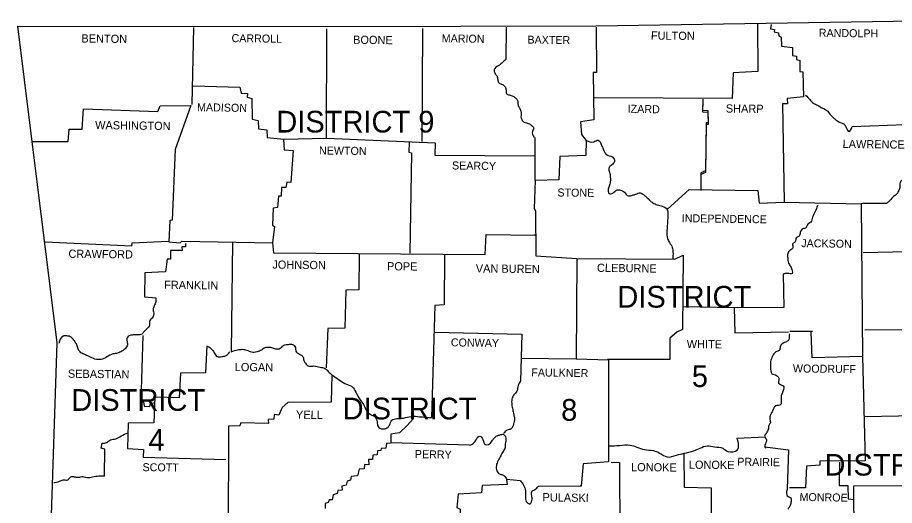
# Model space of a CAD drawing. Extents: x -42408 to 34530, y -43140 to 20491.
# Drawn here: x -17668 to -15135, y 4456 to 5867 of the extents above; entities that cross this region are included whole.
import ezdxf

# ---------------------------------------------------------------- set-up
doc = ezdxf.new("R2010")
doc.units = 0
for name, color, linetype in [('1', 7, 'Continuous'), ('2', 7, 'Continuous'), ('3', 7, 'Continuous')]:
    doc.layers.add(name, color=color, linetype=linetype)

msp = doc.modelspace()

# ---------------------------------------------------------------- linework, layer by layer
at = {"layer": '1'}
msp.add_line((-15436.7, 4960.3), (-15371.2, 4960.3), dxfattribs=at)
for points in [[(-17667.8, 5841.4), (-16777.9, 5840.9), (-15996.9, 5842.5), (-15075.6, 5856.8), (-14648.6, 5866.7)], [(-17667.8, 5841.4), (-17553.9, 4926.7), (-17603.4, 3433.6)], [(-17159.8, 5838.1), (-17164.8, 5615.2)], [(-17160.9, 5669.7), (-17025.5, 5665.3), (-17022.2, 5647.7), (-17003.5, 5647.2), (-17004.1, 5636.1), (-16990.9, 5632.8), (-16989.8, 5572.9), (-16972.7, 5569), (-16971.6, 5545.3), (-16947.4, 5542), (-16946.3, 5520), (-16898.4, 5515.1), (-16775.1, 5517.8), (-16774, 5834.3)], [(-16498.3, 5835.4), (-16500, 5508.5)], [(-16256.1, 5839.2), (-16257.2, 5745.1)], [(-15996.9, 5839.2), (-15995.8, 5708.2), (-16005.2, 5707.7), (-16003.5, 5570.7), (-16042.1, 5565.2), (-16038.8, 5528.3), (-16025.5, 5511.2), (-16026.6, 5467.7), (-16101.5, 5465), (-16104.2, 5397.8), (-16172.5, 5395.6), (-16175.8, 5314.2), (-16171.9, 5307.6), (-16170.3, 5177.7), (-16052.5, 5170), (-16054.2, 4880), (-15960.6, 4877.2), (-15960.6, 4582.2), (-16034.4, 4576.7), (-16039.9, 4511.8), (-16163.7, 4511.2)], [(-15530.8, 5847.5), (-15529.7, 5711), (-15601.2, 5707.1), (-15603.4, 5632.3), (-16001.3, 5634.5)], [(-15491.2, 5846.9), (-15492.8, 5833.7), (-15481.8, 5832.1), (-15482.3, 5825.5), (-15469.7, 5822.7), (-15468.6, 5813.9), (-15462.5, 5810.1), (-15460.9, 5783.6), (-15429.5, 5780.3), (-15429.5, 5756.7), (-15418, 5755), (-15418, 5745.7), (-15408, 5742.9), (-15408.6, 5711), (-15399.8, 5709.3), (-15397.6, 5637.2), (-15444.4, 5632.8), (-15443.8, 5617.4), (-15458.1, 5616.9), (-15453.2, 5332.9), (-15231.4, 5327.9), (-15227.5, 4886.6), (-15372.3, 4882.7), (-15375, 4957)], [(-15688.2, 5630.6), (-15689.3, 5598.7), (-15673.9, 5597.6), (-15673.3, 5562.4), (-15678.8, 5562.4), (-15681, 5423.7), (-15693.7, 5418.2), (-15693.7, 5372)], [(-15688.2, 5625.7), (-15689.3, 5593.8), (-15673.9, 5592.7), (-15673.3, 5557.4), (-15678.8, 5557.4), (-15681, 5418.8), (-15693.7, 5413.3), (-15693.7, 5367)], [(-15619.4, 5629.5), (-15618.8, 5630.1)], [(-17624.3, 5508.5), (-17521.4, 5507.9), (-17518.7, 5544.2), (-17480.7, 5544.2), (-17477.4, 5603.1), (-17262.7, 5595.4), (-17256.1, 5611.9), (-17167.5, 5612.5), (-17212.1, 5484.8), (-17220.9, 5280.6), (-17227.5, 5280.1), (-17230.8, 5218.4), (-17198.4, 5215.7), (-17193.4, 5220.6), (-16930.9, 5215.7), (-16928.1, 5186.5)], [(-15257.3, 5551.9), (-15053.1, 5559.1)], [(-16899.5, 5514), (-16897.3, 5484.3), (-16872, 5482.6), (-16878.6, 5390.1), (-16890.2, 5390.7), (-16892.4, 5375.8), (-16905.6, 5375.8), (-16906.1, 5350.5), (-16914.4, 5350), (-16917.1, 5317.5), (-16929.2, 5315.8), (-16930.9, 5266.3), (-16925.4, 5262.5), (-16930.9, 5215.7)], [(-16775.1, 5517.8), (-16461.4, 5504.6), (-16462, 5468.8), (-16174.1, 5466.6)], [(-16536.8, 5506.3), (-16537.4, 5477.6), (-16530.2, 5476), (-16534.6, 5185.4)], [(-16172.5, 5395.6), (-16173, 5519.5)], [(-15790.5, 5313.1), (-15727.8, 5369.8), (-15529.7, 5367), (-15525.8, 5330.2), (-15453.7, 5332.9)], [(-15159.3, 5329.1), (-15226.4, 5329.1), (-15231.4, 5327.9)], [(-17588, 5217.9), (-17337.6, 5206.3), (-17336.5, 5215.1), (-17231.9, 5220.1)], [(-17046.5, 5217.9), (-17050.3, 4900.3)], [(-16928.1, 5186.5), (-16317.2, 5181.6), (-16314.5, 5239.3), (-16172.5, 5237.7)], [(-16174.1, 5238.2), (-16172.5, 5239.9)], [(-17182.4, 5213.5), (-17182.4, 5203.6), (-17192.8, 5203.6), (-17192.3, 5193.7), (-17225.9, 5193.1), (-17226.4, 5168.3), (-17235.8, 5168.3), (-17240.7, 5131.5), (-17300.2, 5128.7), (-17300.7, 5058.8), (-17268.8, 5056.6)], [(-14718.5, 5198.1), (-15225.3, 5186.5)], [(-16681, 5182.1), (-16681.6, 5079.2), (-16719.5, 5078.6), (-16722.8, 4969.1), (-16771.3, 4967.5), (-16776.8, 4854.1)], [(-16434.5, 5179.4), (-16435.6, 5036.3), (-16462, 5034.1), (-16472.4, 4710.5)], [(-16052.5, 5170), (-15769.6, 5168.3), (-15745.4, 5179.9), (-15747.1, 4964.7), (-15763.6, 4957.6), (-15778.4, 4944.9), (-15783.4, 4940), (-15783.9, 4878.3), (-15963.9, 4878.3)], [(-15455.9, 5124.9), (-15454.8, 5028), (-15597.9, 5027.5), (-15744.9, 5030.2)], [(-15597.9, 5027.5), (-15595.7, 4955.4), (-15441.1, 4958.1)], [(-15220.9, 4963.6), (-15008.5, 4964.7), (-15007.9, 4972.4), (-14934.2, 4977.9), (-14934.2, 4966.4), (-14613.9, 4975.2)], [(-17306.2, 4947.7), (-17311.7, 4758.3), (-17303.5, 4756.1), (-17301.8, 4742.9), (-17285.3, 4741.8), (-17283.7, 4751.2), (-17270.4, 4753.4)], [(-16463.1, 4957.6), (-16211.6, 4951.5), (-16214.9, 4815.6)], [(-15436.7, 4951), (-15439.4, 4950.4)], [(-17121.3, 4917.9), (-17125.2, 4839.2), (-17196.7, 4838.7), (-17200.6, 4767.1), (-17271.5, 4768.8), (-17273.7, 4695), (-17348, 4694.5), (-17350.2, 4620.7), (-17303.5, 4618), (-17305.1, 4595.4), (-17066.3, 4588.8)], [(-16214.3, 4882.2), (-16054.2, 4880)], [(-15227.5, 4886.6), (-15219.3, 4585), (-15350.3, 4584.4), (-15350.8, 4572.3), (-15388.8, 4570.1), (-15392.1, 4507.4), (-15438.3, 4507.4)], [(-16759.7, 4833.7), (-16761.9, 4754.5), (-16887.4, 4753.9), (-16903.9, 4739.6), (-16913.3, 4717.6), (-16927, 4718.7), (-16927.6, 4706), (-16943.5, 4704.4), (-16943, 4692.8), (-17022.8, 4695), (-17025.5, 4686.2), (-17058.6, 4685.1), (-17059.7, 4363.2)], [(-15220.9, 4713.2), (-14783.9, 4722)], [(-16523.6, 4708.3), (-16543.4, 4686.8), (-16564.9, 4666.4), (-16589.7, 4662.6), (-16589.7, 4636.7), (-16601.8, 4635.1), (-16604, 4621.8), (-16617.7, 4620.7), (-16618.8, 4614.7), (-16628.2, 4614.1), (-16628.7, 4602.6), (-16641.9, 4602), (-16643, 4588.8), (-16654.1, 4588.8), (-16653.5, 4573.4), (-16665.6, 4574.5), (-16666.2, 4562.4), (-16681, 4561.3), (-16685.4, 4541.5), (-16704.1, 4539.8), (-16705.8, 4528.8), (-16715.7, 4526.1), (-16718.4, 4514.5), (-16731.1, 4511.8), (-16730, 4500.2), (-16742.7, 4499.1), (-16744.9, 4490.3), (-16756.4, 4487), (-16759.2, 4472.1), (-16768, 4472.7), (-16770.7, 4465), (-16779, 4462.2), (-16779.5, 4447.4)], [(-17416.8, 4540.9), (-17415.2, 4618.5), (-17426.2, 4621.8), (-17422.9, 4636.7)], [(-16362.4, 4630.1), (-16589.1, 4637.3)], [(-15589.1, 4650.5), (-15508.8, 4654.3)], [(-15509.3, 4625.7), (-15440.5, 4616.9), (-15444.4, 4504.6)], [(-15743.2, 4605.5), (-15742.1, 4509), (-15664.5, 4507.4), (-15664, 4296)], [(-15952.9, 4581.7), (-15928.7, 4580), (-15928.1, 4369.8), (-15956.8, 4250.4), (-15895.7, 4247.6), (-15896.2, 4142.4)], [(-15294.1, 4581.7), (-15294.7, 4513.4), (-15269.4, 4513.4), (-15268.3, 4475.5), (-15252.3, 4473.8)], [(-16215.4, 4527.2), (-16255, 4531.6), (-16253.4, 4516.7), (-16325.5, 4514), (-16327.7, 4492.5), (-16395.4, 4488.7), (-16399.2, 4450.1), (-16389.3, 4445.2), (-16389.3, 4420.6)], [(-16042.6, 4512.3), (-16039.9, 4515.1)], [(-15220.9, 4025.3), (-15178, 4028), (-15178.6, 4139.7), (-15218.7, 4142.5), (-15216.5, 4361), (-15251.2, 4365.9), (-15252.3, 4512.9), (-14782.8, 4516.2)]]:
    msp.add_lwpolyline(points, dxfattribs=at)
for points in [[(-16257.2, 5745.1), (-16267.2, 5736.9), (-16276, 5729.2), (-16289.2, 5719.8), (-16290.8, 5711), (-16286.4, 5702.2), (-16282, 5695), (-16280.4, 5685.1), (-16276.5, 5676.9), (-16267.2, 5673.6), (-16259.4, 5666.4), (-16256.7, 5656.5), (-16255.6, 5647.2), (-16246.8, 5642.8), (-16236.9, 5639.5), (-16227.5, 5632.8), (-16223.1, 5624.6), (-16222, 5614.1), (-16218.2, 5605.9), (-16213.8, 5596), (-16212.7, 5587.7), (-16213.8, 5579.5), (-16211.6, 5571.8), (-16204.4, 5564.1), (-16191.8, 5560.2), (-16182.9, 5554.7), (-16176.9, 5547), (-16180.7, 5537.6), (-16180.2, 5529.4), (-16175.2, 5519.5)], [(-15391.5, 5642.2), (-15379.4, 5629.5), (-15369, 5619.1), (-15356.9, 5613), (-15342.6, 5604.8), (-15329.9, 5598.2), (-15321.6, 5587.7), (-15310.1, 5576.2), (-15298.5, 5566.8), (-15280.4, 5558), (-15274.3, 5548.6), (-15266.1, 5537.1), (-15257.3, 5551.9)], [(-15054.7, 5558.5), (-15063, 5545.3), (-15069.6, 5529.9), (-15082.8, 5512.3), (-15092.7, 5495.3), (-15094.3, 5483.7), (-15102.1, 5468.3), (-15106.5, 5452.9), (-15111.4, 5439.7), (-15111.4, 5425.9), (-15107.6, 5412.2), (-15108.7, 5399.5), (-15116.9, 5393.4), (-15119.1, 5377.5), (-15122.4, 5366.5), (-15129.6, 5355.5), (-15140, 5347.2), (-15151, 5334.6), (-15159.3, 5329.1)], [(-16025.5, 5511.2), (-16003.5, 5507.4), (-15990.3, 5512.3), (-15981, 5498), (-15976, 5487), (-15967.8, 5471), (-15954.6, 5466.1), (-15944.6, 5457.3), (-15944.6, 5447.9), (-15953.4, 5439.1), (-15960.1, 5430.3), (-15957.9, 5419.9), (-15955.7, 5405.5), (-15955.7, 5391.8), (-15959, 5379.1), (-15961.7, 5367.6), (-15959, 5357.7), (-15948.5, 5359.3), (-15937.5, 5367.6), (-15925.9, 5367.6), (-15914.9, 5361.5), (-15903.4, 5351.1), (-15891.8, 5353.3), (-15882.5, 5356), (-15869.2, 5359.9), (-15859.9, 5354.9), (-15851.6, 5348.3), (-15841.7, 5337.9), (-15832.4, 5331.3), (-15820.3, 5325.2), (-15805.4, 5321.3), (-15791.6, 5312), (-15789.4, 5296), (-15790, 5282.3), (-15791.1, 5265.2), (-15792.2, 5246.5), (-15790.5, 5228.3), (-15784.5, 5216.2), (-15776.8, 5201.9), (-15774.6, 5188.7), (-15775.1, 5167.8)], [(-15357.4, 5323), (-15364, 5305.9), (-15371.7, 5289.4), (-15376.7, 5275.1), (-15387.1, 5266.9), (-15390.4, 5259.2), (-15399.8, 5255.9), (-15406.9, 5244.8), (-15410.3, 5234.9), (-15418, 5230.5), (-15421.8, 5218.4), (-15429, 5211.8), (-15428.4, 5200.8), (-15436.7, 5193.1), (-15443.3, 5184.3), (-15443.3, 5172.2), (-15440.5, 5156.2), (-15435, 5146.9), (-15430.1, 5134.8), (-15430.6, 5127.1), (-15444.4, 5127.1), (-15455.9, 5124.9)], [(-17268.8, 5056.6), (-17268.8, 5045.1), (-17273.2, 5033), (-17275.9, 5022.5), (-17274.3, 5008.7), (-17279.3, 4997.7), (-17286.4, 4988.9), (-17286.4, 4977.9), (-17294.7, 4966.4), (-17303.5, 4957.6), (-17311.2, 4950.4), (-17324.9, 4949.3), (-17336.5, 4948.8), (-17348, 4944.9), (-17352.4, 4936.6), (-17350.2, 4924), (-17354.7, 4911.9), (-17366.2, 4902.5), (-17378.9, 4896.5), (-17392.1, 4894.3), (-17410.2, 4885.5), (-17426.7, 4878.3), (-17444.4, 4879.4), (-17460.9, 4886.6), (-17475.7, 4893.2), (-17487.3, 4899.8), (-17496.6, 4920.1), (-17502.7, 4931.1), (-17513.2, 4942.2), (-17525.8, 4946.6), (-17536.3, 4945.5), (-17548.9, 4924)], [(-15439.4, 4950.4), (-15442.2, 4932.2), (-15452.6, 4927.3), (-15464.7, 4915.2), (-15467.5, 4904.2), (-15477.4, 4899.8), (-15486.7, 4888.2), (-15492.8, 4872.3), (-15492.8, 4855.7), (-15489, 4837), (-15475.2, 4832.1), (-15468.6, 4821.1), (-15469.7, 4809.5), (-15456.5, 4801.8), (-15454.3, 4795.2), (-15456.5, 4788.1), (-15462.5, 4767.7), (-15462, 4753.9), (-15463.1, 4747.9), (-15477.9, 4744), (-15486.7, 4729.2), (-15492.8, 4718.7), (-15495, 4704.9), (-15493.4, 4695), (-15497.8, 4687.3), (-15499.4, 4675.8), (-15504.9, 4665.9), (-15509.9, 4656.5), (-15504.4, 4645.5), (-15506, 4637.8), (-15509.3, 4625.7), (-15506.6, 4621.8)], [(-17121.3, 4917.9), (-17109.2, 4910.2), (-17099.8, 4897.6), (-17091.6, 4887.1), (-17077.8, 4886.6), (-17066.8, 4888.8), (-17054.2, 4899.8)], [(-17050.3, 4900.3), (-17032.1, 4906.4), (-17018.9, 4907.5), (-17005.7, 4905.3), (-16992, 4899.8), (-16977.1, 4900.9), (-16966.1, 4904.7), (-16955.1, 4911.9), (-16943, 4914.1), (-16931.4, 4911.9), (-16919.3, 4908.6), (-16906.1, 4912.4), (-16898.4, 4919.6), (-16885.2, 4921.8), (-16873.6, 4921.8), (-16865.4, 4912.4), (-16863.7, 4902.5), (-16853.3, 4893.2), (-16843.9, 4887.1), (-16841.2, 4875.6), (-16836.2, 4867.3), (-16831.3, 4861.8), (-16824.1, 4858.5), (-16812, 4859.6), (-16793.3, 4855.7), (-16781.2, 4853), (-16770.2, 4843.6), (-16759.7, 4833.7)], [(-16759.7, 4833.7), (-16740.5, 4820.5), (-16722.3, 4809), (-16703.6, 4800.7), (-16693.1, 4788.6), (-16683.8, 4769.9), (-16676.1, 4758.3), (-16666.2, 4744), (-16659, 4728.1), (-16647.4, 4719.3), (-16635.3, 4711.6), (-16629.3, 4697.8), (-16626.5, 4684), (-16613.3, 4677.4), (-16600.7, 4680.2), (-16593.5, 4688.4), (-16586.9, 4702.7), (-16572, 4707.2), (-16552.8, 4708.8), (-16530.8, 4713.8), (-16506.6, 4712.7), (-16472.4, 4710.5)], [(-16214.9, 4815.6), (-16222, 4802.9), (-16225.3, 4786.4), (-16234.1, 4775.9), (-16239.6, 4763.8), (-16240.2, 4747.9), (-16237.4, 4733.6), (-16234.7, 4719.8), (-16232.5, 4707.2), (-16235.2, 4691.2), (-16242.4, 4677.4), (-16253.4, 4673.6), (-16263.8, 4664.2)], [(-17422.9, 4636.7), (-17410.8, 4637.8), (-17399.2, 4645.5), (-17383.8, 4648.8), (-17368.4, 4657.1), (-17349.1, 4665.9)], [(-16362.4, 4630.1), (-16348.6, 4637.8), (-16341.4, 4649.4), (-16332.6, 4656.5), (-16323.8, 4646.6), (-16316.1, 4632.3), (-16307.9, 4632.3), (-16297.4, 4642.2), (-16290.8, 4651), (-16282.6, 4657.6), (-16273.8, 4660.4), (-16264.4, 4661.5), (-16257.2, 4651), (-16259.4, 4634.5), (-16259.4, 4623.5), (-16265.5, 4611.9), (-16272.1, 4599.8), (-16279.3, 4586.1), (-16284.8, 4571.2), (-16283.7, 4556.9), (-16276, 4547.5), (-16267.2, 4544.8), (-16255, 4532.7)], [(-15960.6, 4628.4), (-15928.7, 4629.6), (-15898.4, 4630.7), (-15879.2, 4625.1), (-15857.1, 4618), (-15831.3, 4614.7), (-15813.1, 4607.5), (-15791.6, 4596.5), (-15764.1, 4601.5), (-15742.7, 4607), (-15714.6, 4614.1), (-15696.4, 4621.8), (-15675.5, 4628.5), (-15654.6, 4625.7), (-15630.9, 4621.3), (-15616.1, 4612.5), (-15589.1, 4616.3), (-15589.1, 4650.5)], [(-17416.8, 4540.9), (-17432.8, 4540.4), (-17451, 4538.2), (-17467.5, 4536), (-17482.3, 4538.7), (-17496.1, 4536.5), (-17505.4, 4538.7), (-17517, 4536), (-17523.6, 4529.4), (-17537.4, 4529.4), (-17547.3, 4525), (-17563.2, 4521.1)], [(-16215.4, 4527.2), (-16206.1, 4515.1), (-16200.6, 4498.6), (-16200.6, 4479.9), (-16196.2, 4464.4), (-16187.4, 4461.1), (-16181.8, 4474.4), (-16182.9, 4487.6), (-16182.9, 4495.3), (-16173.6, 4501.9), (-16163.7, 4511.2)], [(-15444.4, 4504.6), (-15446.6, 4493.6), (-15442.2, 4482.1), (-15434.5, 4478.2), (-15433.4, 4467.2), (-15436.1, 4456.2), (-15438.3, 4451.8), (-15443.3, 4445.2)]]:
    msp.add_spline(points, degree=3, dxfattribs=at)

# ---------------------------------------------------------------- texts
at = {"layer": '2'}
for s, height, rotation, p in [('FULTON', 23.66, 359.4996, (-15838.4, 5802.9)), ('RANDOLPH', 23.11, 359.2583, (-15353.6, 5811.2)), ('BENTON', 23.67, 359.2527, (-17483.4, 5794.6)), ('CARROLL', 23.11, 359.1481, (-17049.8, 5795.8)), ('BOONE', 23.67, 359.4001, (-16698.6, 5790.8)), ('MARION', 23.11, 359.1854, (-16442.7, 5795.2)), ('BAXTER', 23.11, 359.2559, (-16195.1, 5791.3)), ('MADISON', 23.11, 359.0906, (-17149.4, 5596)), ('IZARD', 23.11, 358.9258, (-15905.6, 5591.6)), ('SHARP', 23.66, 359.3905, (-15622.1, 5592.1)), ('WASHINGTON', 23.66, 359.232, (-17443.8, 5544.2)), ('LAWRENCE', 23.67, 359.2678, (-15284.8, 5489.8)), ('NEWTON', 23.11, 359.2717, (-16797.1, 5471)), ('SEARCY', 23.11, 359.2527, (-16413, 5427.6)), ('STONE', 23.11, 359.4001, (-16108.6, 5349.4)), ('INDEPENDENCE', 23.108, 359.2187, (-15749.3, 5275.1)), ('JACKSON', 23.11, 359.1352, (-15404.2, 5203)), ('CRAWFORD', 23.66, 359.2771, (-17520.9, 5172.2)), ('JOHNSON', 23.67, 359.3514, (-16932, 5140.8)), ('POPE', 23.67, 359.6155, (-16600.7, 5135.9)), ('VAN BUREN', 23.67, 359.3508, (-16344.2, 5129.8)), ('CLEBURNE', 23.66, 359.2535, (-15994.2, 5131.5)), ('FRANKLIN', 23.67, 359.1815, (-17244.6, 5082.5)), ('CONWAY', 23.11, 359.0371, (-16416.3, 4916.3)), ('WHITE', 23.67, 359.3139, (-15735, 4911.3)), ('LOGAN', 23.67, 359.3969, (-17040.4, 4844.7)), ('WOODRUFF', 23.11, 359.2748, (-15428.4, 4840.9)), ('SEBASTIAN', 23.66, 359.2816, (-17522.5, 4825.5)), ('FAULKNER', 23.11, 359.2486, (-16184, 4829.3)), ('YELL', 23.67, 359.1987, (-16863.7, 4707.2)), ('PERRY', 23.11, 359.0858, (-16520.3, 4593.2)), ('LONOKE', 23.67, 359.4974, (-15728.9, 4562.4)), ('PRAIRIE', 23.11, 359.2116, (-15589.1, 4571.2)), ('SCOTT', 23.11, 359.4063, (-17306.8, 4555.3)), ('LONOKE', 23.67, 359.4974, (-15895.7, 4555.3)), ('PULASKI', 23.67, 359.053, (-16151.6, 4468.3)), ('MONROE', 23.11, 359.0331, (-15409.1, 4469.4))]:
    msp.add_text(s, height=height, rotation=rotation, dxfattribs=at).set_placement(p)
at = {"layer": '3'}
for s, height, p in [('DISTRICT 9', 62.74, (-16920.4, 5534.3)), ('DISTRICT', 62.74, (-15935.3, 5028)), ('5', 62.7, (-15720.1, 4798.5)), ('DISTRICT', 62.74, (-17512.6, 4729.7)), ('DISTRICT', 62.74, (-16728.9, 4704.9)), ('8', 62.7, (-16097.6, 4701.1)), ('4', 62.7, (-17289.7, 4614.1)), ('DISTRICT', 62.74, (-15337.1, 4542.6))]:
    msp.add_text(s, height=height, dxfattribs=at).set_placement(p)

doc.saveas('drawing.dxf')
